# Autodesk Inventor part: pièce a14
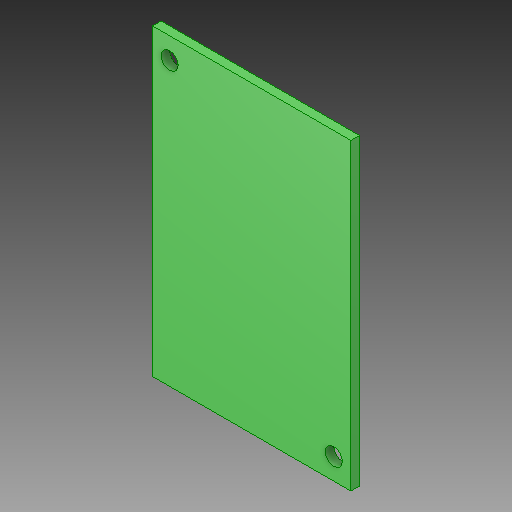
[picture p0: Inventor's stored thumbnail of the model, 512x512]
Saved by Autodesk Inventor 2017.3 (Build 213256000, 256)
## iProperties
Created: 2007-12
Part Number: pièce a14
Material: solidworks materials|PP copolymère|43
Document SubType Name: Modeling
Designer: ficho
Appearance: 0,192,0
Author: ficho
Sending System: SolidWorks 2009
Last Author: christophe
Last Saved: 2011-02-10
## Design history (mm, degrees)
feature "Enlèv. mat.-Extru.1"
node "Solide1"
